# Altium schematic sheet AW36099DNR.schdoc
size 127 x 101 mm
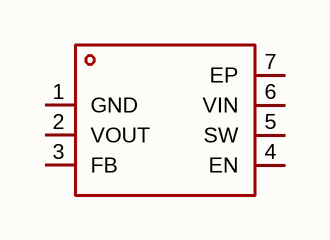
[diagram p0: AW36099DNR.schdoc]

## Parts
U?  aw36099dnr  [TDFN-6_L2.0-W2.0-P0.65-BL-EP]  (value not drawn)

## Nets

Not connected (* = marked no-connect by the designer): U? 1(GND) 2(VOUT) 3(FB) 4(EN) 5(SW) 6(VIN) 7(EP)

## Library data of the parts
U? = aw36099dnr: 功能类型:升压型;工作电压:800mV~5.2V;输出电压:2.5V~5.5V;输出电流:500mA;输出类型:可调;; Manufacturer: AWINIC(艾为); AddInBom: yes; ModelId: cf7eaf10a6c84f09add415985fbe5dc3; ModelName: TDFN-6_L2.0-W2.0-H0.8-P0.65; ModelTransform: 79.527,78.74,0,90,0,0,0,0.0005,0; Function: 升压型; Output Current: 500mA; Synchronous Rectifier: 是; Number of Outputs: 1; Topology: 升压式; Quiescent Current: 350nA; Switch tube (built-in/external): 内置; Output Type: 可调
